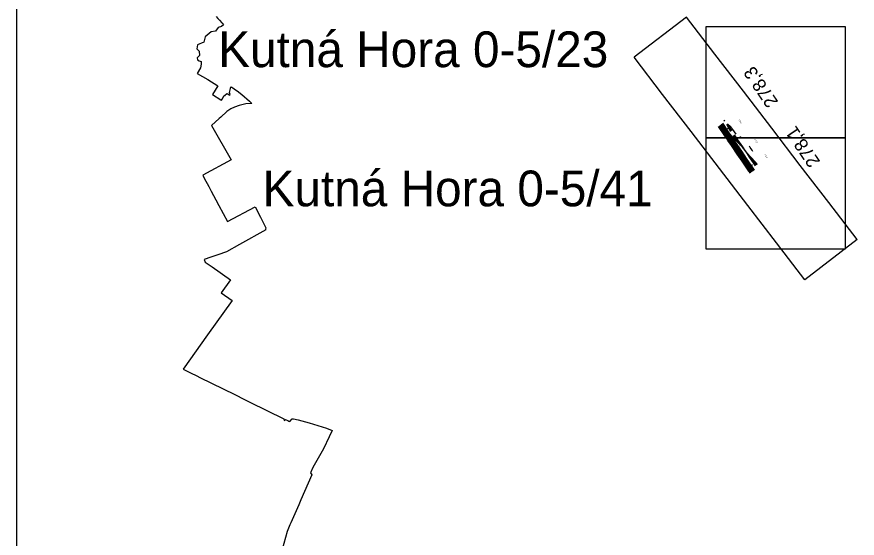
# Model space of a CAD drawing. Extents: x -679349 to -666749, y -1075296 to -1066386.
# Drawn here: x -679349 to -675571, y -1072799 to -1070456 of the extents above; entities that cross this region are included whole.
import ezdxf

# ---------------------------------------------------------------- set-up
doc = ezdxf.new("R2010")
doc.units = 0
for name, color, linetype in [('Default', 7, 'Continuous'), ('DZ_NAD_ostatní', 7, 'Continuous'), ('legenda_text', 7, 'Continuous')]:
    doc.layers.add(name, color=color, linetype=linetype)

msp = doc.modelspace()

# ---------------------------------------------------------------- linework, layer by layer
at = {"layer": 'Default'}
for p, q in [((-676338.2, -1070457.2), (-676573.8, -1070638)), ((-676210.4, -1070623.8), (-676338.2, -1070457.2)), ((-676082.5, -1070790.4), (-676210.4, -1070623.8)), ((-676446, -1070804.6), (-676573.8, -1070638)), ((-676318.1, -1070971.2), (-676446, -1070804.6)), ((-675954.7, -1070957), (-676082.5, -1070790.4)), ((-676165.6, -1070923.9), (-676167.3, -1070920.2)), ((-676190.3, -1071137.8), (-676318.1, -1070971.2)), ((-676155, -1070958.6), (-676155, -1070958.5)), ((-676151.5, -1070944.6), (-676148.7, -1070942.3)), ((-676151.1, -1070945.1), (-676148.3, -1070942.7)), ((-676149.7, -1070953.9), (-676146.5, -1070951.9)), ((-676149.3, -1070954.4), (-676146.2, -1070952.4)), ((-675826.8, -1071123.6), (-675954.7, -1070957)), ((-676175.6, -1070977.2), (-676172.3, -1070975.2)), ((-676175.3, -1070977.7), (-676172, -1070975.8)), ((-676163.8, -1070992.3), (-676160.6, -1070990.4)), ((-676163.5, -1070992.8), (-676160.2, -1070990.9)), ((-676125.2, -1071008.6), (-676121.9, -1071005.9)), ((-676124.8, -1071009.1), (-676121.5, -1071006.4)), ((-676114.7, -1071013.7), (-676111.8, -1071011.3)), ((-676114.3, -1071014.2), (-676111.4, -1071011.8)), ((-676100.3, -1071026.3), (-676097.3, -1071024)), ((-676100, -1071026.7), (-676097, -1071024.5)), ((-676099, -1071038.8), (-676099, -1071038.7)), ((-676061, -1071073), (-676064, -1071069.6)), ((-676055.1, -1071085.8), (-676051.8, -1071083.5)), ((-676054.8, -1071086.3), (-676051.5, -1071083.9)), ((-676043.8, -1071122.1), (-676043.9, -1071122)), ((-675699, -1071290.2), (-675826.8, -1071123.6)), ((-676062.5, -1071304.4), (-676190.3, -1071137.8)), ((-675934.6, -1071471), (-676062.5, -1071304.4)), ((-675571.2, -1071456.8), (-675699, -1071290.2)), ((-675571.2, -1071456.8), (-675806.8, -1071637.6)), ((-675806.8, -1071637.6), (-675934.6, -1071471))]:
    msp.add_line(p, q, dxfattribs=at)
for points in [[(-675625, -1070500), (-675625, -1071000), (-676250, -1071000), (-676250, -1070500)], [(-675625, -1071000), (-675625, -1071500), (-676250, -1071500), (-676250, -1071000)]]:
    msp.add_lwpolyline(points, close=True, dxfattribs=at)
for points in [[(-676032.1, -1071145), (-676038.3, -1071135.8), (-676068.2, -1071092), (-676090.4, -1071059.5), (-676118.2, -1071018.8), (-676134.5, -1070994.9), (-676143.9, -1070981.1), (-676149.8, -1070972.4), (-676175.7, -1070934.4)], [(-676167.2, -1070925.4), (-676171.2, -1070921.8)], [(-676166.4, -1070990.6), (-676194.9, -1070948.8)], [(-676047.7, -1071156), (-676054.4, -1071146.3), (-676084, -1071102.7), (-676106.2, -1071070.1), (-676132.7, -1071031.4), (-676151.4, -1071003.9), (-676169.2, -1070977.6), (-676176.3, -1070967.2), (-676183.4, -1070956.8), (-676190.9, -1070945.8)], [(-676043.8, -1071153.2), (-676050.4, -1071143.7), (-676080.1, -1071100.1), (-676102.3, -1071067.4), (-676128.7, -1071028.6), (-676147.1, -1071001.7), (-676165.4, -1070974.8), (-676187.1, -1070942.9)], [(-676039.9, -1071150.4), (-676046.2, -1071141.2), (-676076.1, -1071097.3), (-676098.3, -1071064.8), (-676124.6, -1071026.2), (-676143.2, -1070998.9), (-676161.4, -1070972.1), (-676183.3, -1070940.1)], [(-676036, -1071147.7), (-676042.4, -1071138.4), (-676072.3, -1071094.6), (-676094.3, -1071062.1), (-676122.3, -1071021.2), (-676138.3, -1070997.6), (-676157.5, -1070969.4), (-676179.5, -1070937.2)], [(-676159.3, -1071001.1), (-676165, -1070989.8), (-676170.7, -1070978.5), (-676176.3, -1070967.2)], [(-676139, -1070971.3), (-676149.7, -1070953.9), (-676156.7, -1070939.7)], [(-676135.1, -1070968.6), (-676145.9, -1070952.7), (-676155.3, -1070938.9)], [(-676115, -1070983.5), (-676130.5, -1070962.1), (-676141.3, -1070949.5), (-676153.7, -1070937.5)], [(-676051.5, -1071158.6), (-676058.1, -1071149), (-676088.1, -1071105.2), (-676110.4, -1071072.7), (-676136.7, -1071034.3), (-676152.2, -1071011.5), (-676159.3, -1071001.1), (-676166.4, -1070990.6)], [(-676095.1, -1071032.6), (-676104.4, -1071024), (-676114.2, -1071014.4), (-676133.1, -1070993.8), (-676143.9, -1070981.1)], [(-676087.1, -1071042.4), (-676095.1, -1071032.6), (-676103.1, -1071022.9), (-676111.9, -1071011.2), (-676127, -1070988.8)], [(-676028.3, -1071125.1), (-676034.2, -1071116.5), (-676054.9, -1071086.1), (-676065, -1071071.4), (-676075.5, -1071056), (-676086, -1071040.5), (-676108.1, -1071008.2), (-676123.1, -1070986.1)], [(-676094.5, -1070998.2), (-676098.8, -1070994.9)], [(-676024.2, -1071122.7), (-676029, -1071115.6), (-676039.8, -1071100), (-676042.2, -1071096.7), (-676053.2, -1071081.6), (-676061, -1071073), (-676064, -1071069.6), (-676075.5, -1071056), (-676087.1, -1071042.4)], [(-676039.9, -1071061.8), (-676043.8, -1071055.7), (-676052.5, -1071042.5), (-676056, -1071037.2)], [(-676019.2, -1071119.5), (-676030.1, -1071107), (-676036.6, -1071099.9), (-676040.8, -1071095.2), (-676053.2, -1071081.6)]]:
    msp.add_lwpolyline(points, dxfattribs=at)
for centre, radius in [((-676167.7, -1070967.2), 0.75), ((-676155, -1070958.6), 0.5), ((-676099, -1071038.7), 0.5), ((-676043.9, -1071122.1), 0.5), ((-676056.3, -1071130.6), 0.75)]:
    msp.add_circle(centre, radius, dxfattribs=at)
at = {"layer": 'DZ_NAD_ostatní'}
for p, q in [((-678438.4, -1070470.9), (-678427.6, -1070483)), ((-678427.6, -1070483), (-678424.2, -1070486.4)), ((-678424.2, -1070486.4), (-678422.6, -1070488.2)), ((-678422.6, -1070488.2), (-678419.2, -1070492.4)), ((-678529.2, -1070611), (-678528.2, -1070629.2)), ((-678529.1, -1070653.1), (-678519.9, -1070656.9)), ((-678520.6, -1070668.9), (-678523.5, -1070685.7)), ((-678519.9, -1070656.9), (-678520.6, -1070668.9)), ((-678523.5, -1070685.7), (-678537.8, -1070710.3)), ((-678537.8, -1070710.3), (-678490.5, -1070737.1)), ((-678490.5, -1070737.1), (-678446, -1070766.2)), ((-678446, -1070766.2), (-678468.8, -1070805)), ((-678392.3, -1070796.6), (-678388.4, -1070777.6)), ((-678388.4, -1070777.6), (-678387.6, -1070771.3)), ((-678383.3, -1070772.2), (-678382.5, -1070772.7)), ((-678382.5, -1070772.7), (-678378.5, -1070775.4)), ((-678378.5, -1070775.4), (-678365.6, -1070784.2)), ((-678468.8, -1070805), (-678432.6, -1070828.6)), ((-678416.2, -1070808.9), (-678412.5, -1070810.2)), ((-678365.6, -1070784.2), (-678359.1, -1070788.7)), ((-678359.1, -1070788.7), (-678337.1, -1070805.5)), ((-678337.1, -1070805.5), (-678303.7, -1070835.2)), ((-678432.6, -1070828.6), (-678429.2, -1070830.8)), ((-678293.2, -1070845.4), (-678318.9, -1070847.1)), ((-678303.7, -1070835.2), (-678293.2, -1070845.4)), ((-678439.2, -1070913.2), (-678474, -1070944.4)), ((-678432.5, -1070906.9), (-678439.2, -1070913.2)), ((-678474, -1070944.4), (-678385.3, -1071098.9)), ((-678385.3, -1071098.9), (-678513.5, -1071166.9)), ((-678513.5, -1071166.9), (-678506.2, -1071180.7)), ((-678506.2, -1071180.7), (-678486.6, -1071217.7)), ((-678486.6, -1071217.7), (-678475.4, -1071238.7)), ((-678475.4, -1071238.7), (-678454.6, -1071277.9)), ((-678454.6, -1071277.9), (-678441.2, -1071303.3)), ((-678441.2, -1071303.3), (-678402.6, -1071375.9)), ((-678402.6, -1071375.9), (-678277.7, -1071309.6)), ((-678277.7, -1071309.6), (-678253.9, -1071356.6)), ((-678253.9, -1071356.6), (-678229.7, -1071404.5)), ((-678230.1, -1071412.6), (-678347.6, -1071479.6)), ((-678229.7, -1071404.5), (-678231.1, -1071410.1)), ((-678476.6, -1071535.8), (-678506.5, -1071546.3)), ((-678506.5, -1071546.3), (-678502.3, -1071557.7)), ((-678502.3, -1071557.7), (-678471.2, -1071579.7)), ((-678471.2, -1071579.7), (-678389.1, -1071638.1)), ((-678389.1, -1071638.1), (-678430.4, -1071695.9)), ((-678430.4, -1071695.9), (-678381.2, -1071730.8)), ((-678381.2, -1071730.8), (-678491.5, -1071885.1)), ((-678491.5, -1071885.1), (-678601.9, -1072039.4)), ((-678601.9, -1072039.4), (-678568.8, -1072055.6)), ((-678568.8, -1072055.6), (-678540.5, -1072069.6)), ((-678540.5, -1072069.6), (-678527, -1072076.2)), ((-678527, -1072076.2), (-678369.7, -1072153.4)), ((-678369.7, -1072153.4), (-678325.1, -1072175.3)), ((-678325.1, -1072175.3), (-678301, -1072187.1)), ((-678301, -1072187.1), (-678148.8, -1072261.8)), ((-678148.8, -1072261.8), (-678146.8, -1072270)), ((-678146.8, -1072270), (-678141.8, -1072265.3)), ((-678141.8, -1072265.3), (-678138.2, -1072267.1)), ((-678138.2, -1072267.1), (-678130.5, -1072270.4)), ((-678130.5, -1072270.4), (-678126.1, -1072272.3)), ((-678126.1, -1072272.3), (-678121.2, -1072274.6)), ((-678121.2, -1072274.6), (-678110.9, -1072262.7)), ((-678022.7, -1072514.2), (-678072.2, -1072626.8)), ((-678028.4, -1072504.7), (-678022.7, -1072514.2)), ((-678072.2, -1072626.8), (-678081.8, -1072648.8)), ((-678081.8, -1072648.8), (-678117.3, -1072729.7)), ((-678117.3, -1072729.7), (-678121.3, -1072738.9)), ((-678140.6, -1072794.8), (-678155.5, -1072849.3))]:
    msp.add_line(p, q, dxfattribs=at)
for points in [[(-678452.8, -1070454.8), (-678444.7, -1070463.8), (-678438.4, -1070470.9)], [(-678419.2, -1070492.4), (-678429.1, -1070499.5), (-678443.2, -1070504.1), (-678455.9, -1070520.2), (-678475.6, -1070522.9), (-678502.1, -1070546.2), (-678508.8, -1070569.9), (-678536.1, -1070582.2), (-678540.2, -1070599.4), (-678529.2, -1070611)], [(-678528.2, -1070629.2), (-678539, -1070640.1), (-678537.1, -1070648.8), (-678529.1, -1070653.1)], [(-678387.6, -1070771.3), (-678385.2, -1070771.8), (-678383.3, -1070772.2)], [(-678429.2, -1070830.8), (-678425.8, -1070825.8), (-678416.2, -1070808.9)], [(-678412.5, -1070810.2), (-678410.8, -1070805.6), (-678404, -1070799.9), (-678391.9, -1070808.5), (-678390.2, -1070804.6), (-678392.3, -1070796.6)], [(-678318.9, -1070847.1), (-678349.5, -1070854.2), (-678371, -1070861.3), (-678387.4, -1070869.4), (-678404.9, -1070880.9), (-678432.5, -1070906.9)], [(-678231.1, -1071410.1), (-678230.8, -1071410.9), (-678230.1, -1071412.6)], [(-678347.6, -1071479.6), (-678406.6, -1071511.6), (-678445.6, -1071525.8), (-678476.6, -1071535.8)], [(-678110.9, -1072262.7), (-678105.1, -1072261.8), (-678084.6, -1072267)], [(-678084.6, -1072267), (-678034.8, -1072280.9), (-677957.6, -1072304), (-677931.6, -1072315.4)], [(-677931.6, -1072315.4), (-677944.5, -1072343.2), (-677970.5, -1072396.8), (-678018.2, -1072480.9), (-678028.4, -1072504.7)], [(-678121.3, -1072738.9), (-678133.5, -1072768.4), (-678140.6, -1072794.8)]]:
    msp.add_lwpolyline(points, dxfattribs=at)
at = {"layer": 'legenda_text'}
for p, q in [((-679349.1, -1075295.8), (-679349.1, -1066385.8)), ((-676338.2, -1070457.2), (-676573.8, -1070638)), ((-676210.4, -1070623.8), (-676338.2, -1070457.2)), ((-676082.5, -1070790.4), (-676210.4, -1070623.8)), ((-676446, -1070804.6), (-676573.8, -1070638)), ((-676318.1, -1070971.2), (-676446, -1070804.6)), ((-675954.7, -1070957), (-676082.5, -1070790.4)), ((-676190.3, -1071137.8), (-676318.1, -1070971.2)), ((-675826.8, -1071123.6), (-675954.7, -1070957)), ((-675699, -1071290.2), (-675826.8, -1071123.6)), ((-676062.5, -1071304.4), (-676190.3, -1071137.8)), ((-675934.6, -1071471), (-676062.5, -1071304.4)), ((-675571.2, -1071456.8), (-675699, -1071290.2)), ((-675571.2, -1071456.8), (-675806.8, -1071637.6)), ((-675806.8, -1071637.6), (-675934.6, -1071471))]:
    msp.add_line(p, q, dxfattribs=at)

# ---------------------------------------------------------------- texts
at = {"layer": 'Default'}
for s, p in [('Kutná Hora 0-5/23', (-678443.8, -1070682.1)), ('Kutná Hora 0-5/41', (-678244.3, -1071307.3))]:
    msp.add_text(s, height=160.495, dxfattribs=at).set_placement(p)
for s, height, rotation, p in [('278,3', 59.67, 124.2428, (-675924.1, -1070838.1)), ('278,3', 6, 124.2428, (-676088.4, -1070933.7)), ('278,1', 59.67, 124.3201, (-675735.4, -1071106.5)), ('278,2', 6, 124.2844, (-676018.5, -1071021.1)), ('278,1', 6, 124.3201, (-675972.5, -1071088.2))]:
    msp.add_text(s, height=height, rotation=rotation, dxfattribs=at).set_placement(p)

doc.saveas('drawing.dxf')
